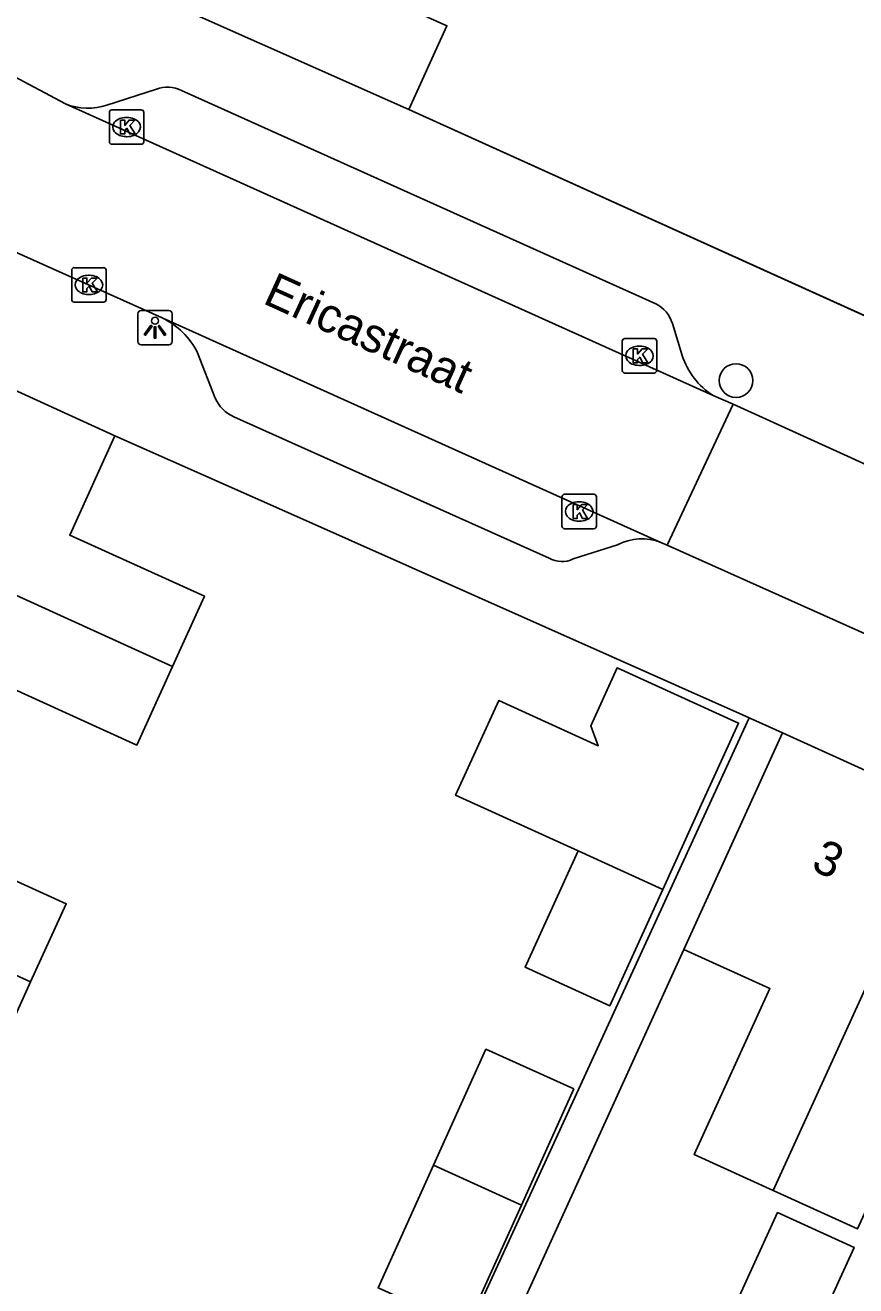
# Model space of a CAD drawing. Extents: x 161845 to 162341, y 381620 to 382158.
# Drawn here: x 162083.32 to 162107.43, y 381710.21 to 381746.81 of the extents above; entities that cross this region are included whole.
import ezdxf

# ---------------------------------------------------------------- set-up
doc = ezdxf.new("R2010")
doc.units = 0
for name, color, linetype in [('IMGEO_Boom', 7, 'Continuous'), ('IMGEO_Kolk', 7, 'Continuous'), ('IMGEO_Lichtpunt', 7, 'Continuous'), ('IMGEO_Muur', 7, 'Continuous'), ('IMGEO_Openbare_ruimte_label', 7, 'Continuous'), ('IMGEO_Pand', 7, 'Continuous'), ('IMGEO_Pand_nummerreeks', 7, 'Continuous'), ('IMGEO_Rijbaan_lokaal_open', 7, 'Continuous'), ('IMGEO_Voetpad_open', 7, 'Continuous')]:
    doc.layers.add(name, color=color, linetype=linetype)

msp = doc.modelspace()

# ---------------------------------------------------------------- linework, layer by layer
at = {"layer": 'IMGEO_Boom'}
msp.add_circle((162103.955, 381736.494), 0.489, dxfattribs=at)
at = {"layer": 'IMGEO_Kolk'}
for p, q in [((162085.84, 381744.356), (162086.692, 381744.356)), ((162085.765, 381743.43), (162085.765, 381744.282)), ((162086.253, 381744.136), (162086.278, 381744.136)), ((162086.766, 381744.282), (162086.766, 381743.43)), ((162086.276, 381743.576), (162086.251, 381743.576)), ((162086.692, 381743.356), (162085.84, 381743.356)), ((162084.671, 381738.846), (162084.671, 381739.698)), ((162084.746, 381739.772), (162085.598, 381739.772)), ((162085.159, 381739.552), (162085.184, 381739.552)), ((162085.672, 381739.698), (162085.672, 381738.846)), ((162085.182, 381738.992), (162085.157, 381738.992)), ((162085.598, 381738.772), (162084.746, 381738.772)), ((162100.727, 381737.713), (162101.579, 381737.713)), ((162100.652, 381736.787), (162100.652, 381737.639)), ((162101.14, 381737.493), (162101.165, 381737.493)), ((162101.653, 381737.639), (162101.653, 381736.787)), ((162101.579, 381736.713), (162100.727, 381736.713)), ((162101.163, 381736.933), (162101.138, 381736.933)), ((162098.902, 381732.266), (162098.902, 381733.118)), ((162098.977, 381733.192), (162099.829, 381733.192)), ((162099.39, 381732.972), (162099.415, 381732.972)), ((162099.903, 381733.118), (162099.903, 381732.266)), ((162099.413, 381732.412), (162099.388, 381732.412)), ((162099.829, 381732.192), (162098.977, 381732.192))]:
    msp.add_line(p, q, dxfattribs=at)
for points in [[(162085.84, 381744.356), (162086.692, 381744.356)], [(162085.765, 381743.43), (162085.765, 381744.282)], [(162086.086, 381744.056), (162086.209, 381744.056), (162086.209, 381743.905), (162086.339, 381744.056), (162086.503, 381744.056), (162086.357, 381743.905), (162086.51, 381743.656), (162086.358, 381743.656), (162086.273, 381743.82), (162086.209, 381743.753), (162086.209, 381743.656), (162086.086, 381743.656), (162086.086, 381744.056)], [(162086.766, 381744.282), (162086.766, 381743.43)], [(162086.692, 381743.356), (162085.84, 381743.356)], [(162084.671, 381738.846), (162084.671, 381739.698)], [(162084.746, 381739.772), (162085.598, 381739.772)], [(162085.672, 381739.698), (162085.672, 381738.846)], [(162084.992, 381739.472), (162085.115, 381739.472), (162085.115, 381739.321), (162085.245, 381739.472), (162085.409, 381739.472), (162085.263, 381739.321), (162085.416, 381739.072), (162085.264, 381739.072), (162085.179, 381739.236), (162085.115, 381739.169), (162085.115, 381739.072), (162084.992, 381739.072), (162084.992, 381739.472)], [(162085.598, 381738.772), (162084.746, 381738.772)], [(162100.727, 381737.713), (162101.579, 381737.713)], [(162100.652, 381736.787), (162100.652, 381737.639)], [(162100.973, 381737.413), (162101.096, 381737.413), (162101.096, 381737.262), (162101.226, 381737.413), (162101.39, 381737.413), (162101.244, 381737.262), (162101.397, 381737.013), (162101.245, 381737.013), (162101.16, 381737.177), (162101.096, 381737.11), (162101.096, 381737.013), (162100.973, 381737.013), (162100.973, 381737.413)], [(162101.653, 381737.639), (162101.653, 381736.787)], [(162101.579, 381736.713), (162100.727, 381736.713)], [(162098.902, 381732.266), (162098.902, 381733.118)], [(162098.977, 381733.192), (162099.829, 381733.192)], [(162099.903, 381733.118), (162099.903, 381732.266)], [(162099.223, 381732.892), (162099.346, 381732.892), (162099.346, 381732.741), (162099.476, 381732.892), (162099.64, 381732.892), (162099.494, 381732.741), (162099.647, 381732.492), (162099.495, 381732.492), (162099.41, 381732.656), (162099.346, 381732.589), (162099.346, 381732.492), (162099.223, 381732.492), (162099.223, 381732.892)], [(162099.829, 381732.192), (162098.977, 381732.192)]]:
    msp.add_lwpolyline(points, dxfattribs=at)
for centre, start, end in [((162085.842, 381744.28), 91.552, 178.448), ((162085.842, 381744.28), 91.552, 178.448), ((162086.69, 381744.28), 1.552, 88.448), ((162086.69, 381744.28), 1.552, 88.448), ((162085.842, 381743.432), 181.552, 268.448), ((162085.842, 381743.432), 181.552, 268.448), ((162086.69, 381743.432), 271.552, 358.448), ((162086.69, 381743.432), 271.552, 358.448), ((162084.748, 381739.696), 91.552, 178.448), ((162084.748, 381739.696), 91.552, 178.448), ((162085.596, 381739.696), 1.552, 88.448), ((162085.596, 381739.696), 1.552, 88.448), ((162084.748, 381738.848), 181.552, 268.448), ((162084.748, 381738.848), 181.552, 268.448), ((162085.596, 381738.848), 271.552, 358.448), ((162085.596, 381738.848), 271.552, 358.448), ((162100.729, 381737.637), 91.552, 178.448), ((162100.729, 381737.637), 91.552, 178.448), ((162101.577, 381737.637), 1.552, 88.448), ((162101.577, 381737.637), 1.552, 88.448), ((162100.729, 381736.789), 181.552, 268.448), ((162100.729, 381736.789), 181.552, 268.448), ((162101.577, 381736.789), 271.552, 358.448), ((162101.577, 381736.789), 271.552, 358.448), ((162098.979, 381733.116), 91.552, 178.448), ((162098.979, 381733.116), 91.552, 178.448), ((162099.827, 381733.116), 1.552, 88.448), ((162099.827, 381733.116), 1.552, 88.448), ((162098.979, 381732.268), 181.552, 268.448), ((162098.979, 381732.268), 181.552, 268.448), ((162099.827, 381732.268), 271.552, 358.448), ((162099.827, 381732.268), 271.552, 358.448)]:
    msp.add_arc(centre, 0.0765, start, end, dxfattribs=at)
for centre, major_axis, ratio, start_param, end_param in [((162086.252, 381743.856), (-0.387, 0.002), 0.722429, 4.712389, 7.853982), ((162086.277, 381743.856), (-0.39, 0.002), 0.717154, 1.570796, 4.712389), ((162085.158, 381739.272), (-0.387, 0.002), 0.722429, 4.712389, 7.853982), ((162085.183, 381739.272), (-0.39, 0.002), 0.717154, 1.570796, 4.712389), ((162101.139, 381737.213), (-0.387, 0.002), 0.722429, 4.712389, 7.853982), ((162101.164, 381737.213), (-0.39, 0.002), 0.717154, 1.570796, 4.712389), ((162099.389, 381732.692), (-0.387, 0.002), 0.722429, 4.712389, 7.853982), ((162099.414, 381732.692), (-0.39, 0.002), 0.717154, 1.570796, 4.712389)]:
    msp.add_ellipse(centre, major_axis=major_axis, ratio=ratio, start_param=start_param, end_param=end_param, dxfattribs=at)
at = {"layer": 'IMGEO_Lichtpunt'}
for p, q in [((162087.493, 381738.529), (162086.685, 381738.529)), ((162087.493, 381738.529), (162086.685, 381738.529)), ((162086.591, 381738.434), (162086.591, 381737.627)), ((162086.591, 381738.434), (162086.591, 381737.627)), ((162087.587, 381737.627), (162087.587, 381738.434)), ((162087.587, 381737.627), (162087.587, 381738.434)), ((162086.685, 381737.533), (162087.493, 381737.533)), ((162086.685, 381737.533), (162087.493, 381737.533))]:
    msp.add_line(p, q, dxfattribs=at)
for points in [[(162086.965, 381738.098), (162087.004, 381738.07), (162086.816, 381737.808), (162086.778, 381737.835), (162086.965, 381738.098)], [(162087.177, 381738.07), (162087.215, 381738.097), (162087.402, 381737.835), (162087.363, 381737.807), (162087.177, 381738.07)], [(162087.067, 381738.05), (162087.114, 381738.05), (162087.114, 381737.728), (162087.067, 381737.728), (162087.067, 381738.05)]]:
    msp.add_lwpolyline(points, dxfattribs=at)
msp.add_circle((162087.09, 381738.232), 0.0994, dxfattribs=at)
for centre, start, end in [((162086.685, 381738.434), 90, 180), ((162086.685, 381738.434), 90, 180), ((162087.493, 381738.434), 0, 90), ((162087.493, 381738.434), 0, 90), ((162086.685, 381737.627), 180, 270), ((162086.685, 381737.627), 180, 270), ((162087.493, 381737.627), 270, 0), ((162087.493, 381737.627), 270, 360)]:
    msp.add_arc(centre, 0.0946, start, end, dxfattribs=at)
at = {"layer": 'IMGEO_Muur'}
for points in [[(162094.462, 381744.361), (162109.441, 381737.584)], [(162085.927, 381734.893), (162090.772, 381732.737)], [(162090.772, 381732.737), (162104.139, 381726.788)]]:
    msp.add_lwpolyline(points, dxfattribs=at)
at = {"layer": 'IMGEO_Pand'}
for points in [[(162091.62, 381751.529), (162090.929, 381750), (162090.511, 381749.074), (162095.561, 381746.795), (162094.462, 381744.361)], [(162083.788, 381749.81), (162086.038, 381748.793), (162085.784, 381748.23), (162094.462, 381744.361)], [(162078.267, 381737.638), (162080.663, 381736.548), (162080.942, 381737.161), (162085.927, 381734.893)], [(162085.927, 381734.893), (162084.615, 381732.008), (162088.528, 381730.228), (162087.601, 381728.189)], [(162087.601, 381728.189), (162076.306, 381733.328)], [(162087.601, 381728.189), (162086.563, 381725.907), (162081.771, 381728.087), (162080.711, 381725.757)], [(162099.37, 381722.834), (162095.816, 381724.45), (162097.067, 381727.201), (162099.956, 381725.888), (162099.736, 381726.467), (162100.504, 381728.155), (162104.03, 381726.549), (162103.369, 381725.098), (162103.005, 381724.3), (162101.828, 381721.716)], [(162102.44, 381719.975), (162103.234, 381721.718), (162105.307, 381726.268)], [(162105.307, 381726.268), (162110.102, 381724.084)], [(162080.711, 381725.757), (162079.684, 381723.498), (162084.511, 381721.303), (162083.477, 381719.029)], [(162072.147, 381724.183), (162083.477, 381719.029)], [(162105.035, 381712.973), (162110.102, 381724.084)], [(162101.828, 381721.716), (162100.289, 381718.336), (162097.831, 381719.455), (162099.37, 381722.834)], [(162099.37, 381722.834), (162101.828, 381721.716)], [(162114.846, 381721.774), (162112.829, 381717.348), (162112.052, 381715.642), (162109.694, 381716.716), (162107.482, 381711.859), (162105.035, 381712.973)], [(162105.035, 381712.973), (162102.742, 381714.018), (162104.938, 381718.838), (162102.44, 381719.975)], [(162083.477, 381719.029), (162082.393, 381716.646), (162077.551, 381718.849), (162076.547, 381716.643)], [(162095.174, 381713.708), (162096.693, 381717.076), (162099.246, 381715.924), (162097.723, 381712.549)], [(162097.723, 381712.549), (162096.119, 381708.994), (162093.567, 381710.146), (162095.174, 381713.708)], [(162097.723, 381712.549), (162095.174, 381713.708)], [(162106.017, 381708.325), (162103.793, 381709.339), (162105.159, 381712.334), (162107.383, 381711.32), (162106.017, 381708.325)]]:
    msp.add_lwpolyline(points, dxfattribs=at)
at = {"layer": 'IMGEO_Rijbaan_lokaal_open'}
for points in [[(162084.495, 381744.526), (162081.506, 381746.115)], [(162103.292, 381736.059), (162084.495, 381744.526)], [(162087.294, 381738.315), (162082.15, 381740.62)], [(162087.294, 381738.315), (162101.774, 381731.795)], [(162103.87, 381735.811), (162103.292, 381736.059)], [(162101.956, 381731.713), (162103.87, 381735.811)], [(162122.654, 381727.261), (162103.87, 381735.811)], [(162101.956, 381731.713), (162101.774, 381731.795)], [(162120.195, 381723.542), (162101.956, 381731.713)]]:
    msp.add_lwpolyline(points, dxfattribs=at)
at = {"layer": 'IMGEO_Voetpad_open'}
for points in [[(162087.13, 381744.956), (162085.696, 381744.492)], [(162101.625, 381738.718), (162087.858, 381744.921)], [(162094.462, 381744.361), (162109.199, 381737.693)], [(162102.389, 381737.226), (162102.106, 381738.152)], [(162088.838, 381735.987), (162088.327, 381737.3)], [(162098.529, 381731.334), (162089.38, 381735.445)], [(162104.332, 381726.702), (162104.139, 381726.788), (162090.772, 381732.737), (162085.927, 381734.893)], [(162100.511, 381731.724), (162099.23, 381731.314)], [(162095.158, 381706.695), (162095.567, 381707.599), (162104.332, 381726.702)], [(162105.307, 381726.268), (162104.332, 381726.702)], [(162094.204, 381700.994), (162093.858, 381701.12), (162102.44, 381719.975)]]:
    msp.add_lwpolyline(points, dxfattribs=at)
for centre, radius, start, end in [((162087.453, 381744.087), 0.927, 64.1074, 110.3876), ((162085.143, 381746.191), 1.787, 248.7297, 288.0272), ((162101.225, 381737.89), 0.919, 16.5286, 64.1887), ((162086.305, 381736.276), 2.266, 26.8698, 64.1373), ((162104.467, 381737.901), 2.185, 197.9997, 237.4641), ((162089.775, 381736.382), 1.017, 202.8684, 247.1316), ((162101.223, 381730.333), 1.563, 69.3442, 117.0908), ((162098.899, 381731.995), 0.758, 240.7934, 295.9381)]:
    msp.add_arc(centre, radius, start, end, dxfattribs=at)

# ---------------------------------------------------------------- texts
at = {"layer": 'IMGEO_Openbare_ruimte_label'}
msp.add_text('Ericastraat', height=1, rotation=335.5371, dxfattribs=at).set_placement((162090.184, 381738.752))
at = {"layer": 'IMGEO_Pand_nummerreeks'}
msp.add_text('3', height=1, rotation=335.5084, dxfattribs=at).set_placement((162106.096, 381722.305))

doc.saveas('drawing.dxf')
